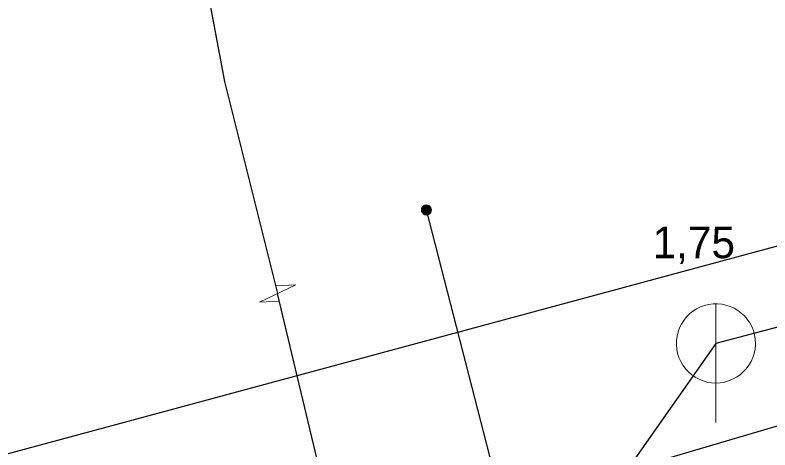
# Model space of a CAD drawing. Extents: x -682839 to -682312, y -994645 to -993949.
# Drawn here: x -682717.39 to -682698.3, y -994076.96 to -994065.98 of the extents above; entities that cross this region are included whole.
import ezdxf

# ---------------------------------------------------------------- set-up
doc = ezdxf.new("R2010")
doc.units = 0
doc.header["$LTSCALE"] = 0.4
doc.layers.add('1', color=7, linetype='Continuous')
for name, color, linetype, lineweight in [('14', 7, 'Continuous', 25), ('17', 7, 'Continuous', 25), ('22', 7, 'Continuous', 13), ('47', 7, 'Continuous', 13), ('9', 7, 'Continuous', 13)]:
    doc.layers.add(name, color=color, linetype=linetype, lineweight=lineweight)

msp = doc.modelspace()

# ---------------------------------------------------------------- linework, layer by layer
at = {"layer": '14'}
msp.add_line((-682699.67, -994074.27), (-682704.43, -994081.039), dxfattribs=at)
msp.add_lwpolyline([(-682670.21, -994066.53), (-682696.629, -994073.469), (-682696.739, -994073.5), (-682699.67, -994074.27)], dxfattribs=at)
at = {"layer": '17'}
for p, q in [((-682705.23, -994077.73), (-682706.989, -994070.899)), ((-682709.273, -994079.188), (-682710.75, -994073.01))]:
    msp.add_line(p, q, dxfattribs=at)
for points in [[(-682704.612, -993949.41), (-682708.09, -993958.105), (-682711.188, -993967.784), (-682713.456, -993979.175), (-682714.892, -993986.737), (-682715.8, -993997.625), (-682717.009, -994008.21), (-682717.083, -994024.577), (-682716.252, -994039.624), (-682714.741, -994053.59), (-682712.096, -994067.653), (-682710.75, -994073.01)], [(-682473.55, -994045.57), (-682522.289, -994043.899), (-682529.616, -994044.905), (-682556.26, -994048.129), (-682661.506, -994061.932), (-682719.074, -994077.464), (-682816.699, -994104.109)], [(-682705.03, -994078.39), (-682696.77, -994075.96), (-682691.829, -994074.544), (-682685.35, -994072.597), (-682672.05, -994068.67), (-682644.92, -994063.19), (-682632.77, -994060.73)]]:
    msp.add_lwpolyline(points, dxfattribs=at)
at = {"layer": '22'}
msp.add_line((-682699.67, -994076.27), (-682699.669, -994073.27), dxfattribs=at)
msp.add_lwpolyline([(-682698.67, -994074.27), (-682698.675, -994074.161), (-682698.693, -994074.053), (-682698.723, -994073.947), (-682698.763, -994073.846), (-682698.815, -994073.749), (-682698.877, -994073.659), (-682698.949, -994073.576), (-682699.029, -994073.502), (-682699.117, -994073.436), (-682699.211, -994073.381), (-682699.311, -994073.336), (-682699.416, -994073.303), (-682699.523, -994073.281), (-682699.632, -994073.271), (-682699.742, -994073.273), (-682699.85, -994073.287), (-682699.957, -994073.312), (-682700.06, -994073.349), (-682700.158, -994073.398), (-682700.25, -994073.456), (-682700.336, -994073.525), (-682700.413, -994073.602), (-682700.482, -994073.688), (-682700.541, -994073.78), (-682700.589, -994073.878), (-682700.626, -994073.981), (-682700.652, -994074.088), (-682700.666, -994074.196), (-682700.669, -994074.306), (-682700.659, -994074.415), (-682700.638, -994074.522), (-682700.604, -994074.626), (-682700.56, -994074.726), (-682700.505, -994074.821), (-682700.439, -994074.909), (-682700.365, -994074.989), (-682700.282, -994075.061), (-682700.192, -994075.123), (-682700.096, -994075.175), (-682699.994, -994075.216), (-682699.889, -994075.246), (-682699.781, -994075.264), (-682699.671, -994075.27), (-682699.562, -994075.264), (-682699.454, -994075.246), (-682699.349, -994075.217), (-682699.247, -994075.176), (-682699.15, -994075.124), (-682699.06, -994075.062), (-682698.977, -994074.991), (-682698.902, -994074.911), (-682698.837, -994074.823), (-682698.781, -994074.729), (-682698.737, -994074.629), (-682698.703, -994074.525), (-682698.681, -994074.417), (-682698.671, -994074.308)], close=True, dxfattribs=at)
at = {"layer": '47'}
msp.add_line((-682710.289, -994072.793), (-682710.799, -994072.815), dxfattribs=at)
msp.add_lwpolyline([(-682710.289, -994072.793), (-682711.21, -994073.226), (-682710.7, -994073.204)], dxfattribs=at)
at = {"layer": '9'}
for points in [[(-682707.115, -994070.899), (-682707.115, -994070.912), (-682707.112, -994070.925), (-682707.11, -994070.938), (-682707.105, -994070.95), (-682707.098, -994070.962), (-682707.092, -994070.973), (-682707.083, -994070.983), (-682707.073, -994070.993), (-682707.063, -994071.001), (-682707.053, -994071.008), (-682707.041, -994071.014), (-682707.029, -994071.019), (-682707.016, -994071.022), (-682707.002, -994071.024), (-682706.99, -994071.026), (-682706.977, -994071.025), (-682706.963, -994071.023), (-682706.951, -994071.02), (-682706.938, -994071.015), (-682706.926, -994071.009), (-682706.916, -994071.002), (-682706.906, -994070.994), (-682706.896, -994070.984), (-682706.887, -994070.974), (-682706.88, -994070.963), (-682706.875, -994070.951), (-682706.87, -994070.939), (-682706.867, -994070.926), (-682706.865, -994070.913), (-682706.862, -994070.9), (-682706.864, -994070.887), (-682706.865, -994070.874), (-682706.869, -994070.861), (-682706.874, -994070.849), (-682706.879, -994070.837), (-682706.887, -994070.826), (-682706.894, -994070.816), (-682706.904, -994070.806), (-682706.914, -994070.798), (-682706.926, -994070.791), (-682706.938, -994070.785), (-682706.95, -994070.78), (-682706.963, -994070.777), (-682706.975, -994070.775), (-682706.989, -994070.774), (-682707.002, -994070.774), (-682707.014, -994070.776), (-682707.027, -994070.779), (-682707.039, -994070.784), (-682707.051, -994070.79), (-682707.063, -994070.797), (-682707.073, -994070.805), (-682707.083, -994070.815), (-682707.09, -994070.825), (-682707.098, -994070.836), (-682707.103, -994070.848), (-682707.108, -994070.86), (-682707.112, -994070.873), (-682707.114, -994070.886)], [(-682707.095, -994070.899), (-682707.095, -994070.91), (-682707.093, -994070.921), (-682707.09, -994070.932), (-682707.087, -994070.942), (-682707.081, -994070.952), (-682707.076, -994070.961), (-682707.068, -994070.97), (-682707.061, -994070.978), (-682707.051, -994070.985), (-682707.043, -994070.991), (-682707.032, -994070.996), (-682707.022, -994071), (-682707.012, -994071.003), (-682707, -994071.006), (-682706.99, -994071.006), (-682706.978, -994071.006), (-682706.968, -994071.004), (-682706.956, -994071.001), (-682706.946, -994070.997), (-682706.936, -994070.992), (-682706.928, -994070.986), (-682706.919, -994070.979), (-682706.911, -994070.971), (-682706.904, -994070.962), (-682706.897, -994070.953), (-682706.892, -994070.943), (-682706.889, -994070.933), (-682706.886, -994070.922), (-682706.884, -994070.911), (-682706.882, -994070.9), (-682706.882, -994070.889), (-682706.884, -994070.878), (-682706.887, -994070.867), (-682706.892, -994070.857), (-682706.897, -994070.847), (-682706.902, -994070.838), (-682706.909, -994070.829), (-682706.918, -994070.821), (-682706.926, -994070.814), (-682706.936, -994070.808), (-682706.946, -994070.803), (-682706.955, -994070.799), (-682706.967, -994070.796), (-682706.977, -994070.794), (-682706.989, -994070.794), (-682707, -994070.793), (-682707.011, -994070.795), (-682707.022, -994070.798), (-682707.031, -994070.802), (-682707.041, -994070.807), (-682707.051, -994070.813), (-682707.059, -994070.82), (-682707.068, -994070.828), (-682707.075, -994070.837), (-682707.08, -994070.846), (-682707.085, -994070.856), (-682707.09, -994070.866), (-682707.093, -994070.877), (-682707.095, -994070.888)], [(-682707.076, -994070.899), (-682707.076, -994070.908), (-682707.075, -994070.917), (-682707.071, -994070.926), (-682707.068, -994070.934), (-682707.065, -994070.942), (-682707.059, -994070.95), (-682707.053, -994070.957), (-682707.048, -994070.963), (-682707.041, -994070.969), (-682707.032, -994070.974), (-682707.024, -994070.978), (-682707.017, -994070.981), (-682707.007, -994070.984), (-682706.999, -994070.985), (-682706.99, -994070.987), (-682706.98, -994070.986), (-682706.972, -994070.985), (-682706.963, -994070.982), (-682706.955, -994070.979), (-682706.946, -994070.975), (-682706.938, -994070.97), (-682706.931, -994070.964), (-682706.926, -994070.958), (-682706.919, -994070.951), (-682706.914, -994070.943), (-682706.911, -994070.935), (-682706.907, -994070.927), (-682706.904, -994070.918), (-682706.904, -994070.909), (-682706.901, -994070.9), (-682706.902, -994070.891), (-682706.904, -994070.882), (-682706.906, -994070.873), (-682706.909, -994070.865), (-682706.914, -994070.857), (-682706.919, -994070.849), (-682706.924, -994070.842), (-682706.931, -994070.836), (-682706.938, -994070.83), (-682706.946, -994070.825), (-682706.953, -994070.821), (-682706.962, -994070.818), (-682706.97, -994070.815), (-682706.98, -994070.814), (-682706.989, -994070.813), (-682706.997, -994070.813), (-682707.007, -994070.814), (-682707.016, -994070.817), (-682707.024, -994070.82), (-682707.031, -994070.824), (-682707.039, -994070.829), (-682707.046, -994070.835), (-682707.053, -994070.841), (-682707.058, -994070.848), (-682707.063, -994070.856), (-682707.068, -994070.864), (-682707.071, -994070.872), (-682707.073, -994070.881), (-682707.075, -994070.89)], [(-682707.056, -994070.899), (-682707.056, -994070.906), (-682707.054, -994070.913), (-682707.053, -994070.92), (-682707.051, -994070.926), (-682707.048, -994070.932), (-682707.044, -994070.938), (-682707.039, -994070.944), (-682707.034, -994070.949), (-682707.029, -994070.953), (-682707.022, -994070.957), (-682707.017, -994070.96), (-682707.011, -994070.963), (-682707.004, -994070.964), (-682706.997, -994070.967), (-682706.99, -994070.967), (-682706.982, -994070.967), (-682706.975, -994070.965), (-682706.968, -994070.964), (-682706.963, -994070.961), (-682706.955, -994070.958), (-682706.951, -994070.954), (-682706.945, -994070.95), (-682706.94, -994070.945), (-682706.936, -994070.939), (-682706.931, -994070.933), (-682706.928, -994070.927), (-682706.926, -994070.921), (-682706.924, -994070.914), (-682706.923, -994070.907), (-682706.921, -994070.9), (-682706.921, -994070.893), (-682706.923, -994070.886), (-682706.924, -994070.879), (-682706.928, -994070.873), (-682706.931, -994070.866), (-682706.934, -994070.861), (-682706.938, -994070.855), (-682706.943, -994070.85), (-682706.95, -994070.846), (-682706.955, -994070.842), (-682706.962, -994070.839), (-682706.968, -994070.836), (-682706.975, -994070.834), (-682706.982, -994070.833), (-682706.989, -994070.833), (-682706.995, -994070.833), (-682707.002, -994070.833), (-682707.009, -994070.835), (-682707.016, -994070.838), (-682707.022, -994070.841), (-682707.027, -994070.845), (-682707.034, -994070.849), (-682707.039, -994070.854), (-682707.043, -994070.86), (-682707.046, -994070.865), (-682707.049, -994070.872), (-682707.053, -994070.878), (-682707.053, -994070.885), (-682707.056, -994070.892)], [(-682707.036, -994070.899), (-682707.036, -994070.904), (-682707.036, -994070.909), (-682707.034, -994070.914), (-682707.032, -994070.918), (-682707.031, -994070.923), (-682707.027, -994070.927), (-682707.024, -994070.93), (-682707.021, -994070.934), (-682707.017, -994070.937), (-682707.014, -994070.94), (-682707.009, -994070.942), (-682707.004, -994070.944), (-682707, -994070.945), (-682706.995, -994070.947), (-682706.99, -994070.947), (-682706.985, -994070.947), (-682706.98, -994070.946), (-682706.975, -994070.945), (-682706.97, -994070.943), (-682706.965, -994070.941), (-682706.962, -994070.938), (-682706.958, -994070.935), (-682706.955, -994070.931), (-682706.951, -994070.928), (-682706.948, -994070.924), (-682706.946, -994070.919), (-682706.945, -994070.915), (-682706.943, -994070.91), (-682706.943, -994070.905), (-682706.941, -994070.9), (-682706.941, -994070.895), (-682706.943, -994070.89), (-682706.943, -994070.885), (-682706.946, -994070.881), (-682706.948, -994070.876), (-682706.951, -994070.872), (-682706.953, -994070.868), (-682706.956, -994070.865), (-682706.96, -994070.862), (-682706.965, -994070.859), (-682706.97, -994070.857), (-682706.973, -994070.855), (-682706.978, -994070.854), (-682706.983, -994070.853), (-682706.989, -994070.853), (-682706.994, -994070.853), (-682706.999, -994070.854), (-682707.004, -994070.854), (-682707.007, -994070.856), (-682707.012, -994070.858), (-682707.017, -994070.861), (-682707.019, -994070.864), (-682707.024, -994070.867), (-682707.026, -994070.871), (-682707.029, -994070.875), (-682707.031, -994070.88), (-682707.034, -994070.884), (-682707.034, -994070.889), (-682707.036, -994070.894)], [(-682707.016, -994070.899), (-682707.016, -994070.902), (-682707.017, -994070.905), (-682707.016, -994070.907), (-682707.014, -994070.91), (-682707.014, -994070.913), (-682707.012, -994070.915), (-682707.009, -994070.917), (-682707.007, -994070.919), (-682707.005, -994070.921), (-682707.004, -994070.923), (-682707, -994070.925), (-682706.997, -994070.926), (-682706.995, -994070.926), (-682706.992, -994070.927), (-682706.99, -994070.927), (-682706.987, -994070.927), (-682706.983, -994070.927), (-682706.98, -994070.926), (-682706.978, -994070.925), (-682706.975, -994070.924), (-682706.973, -994070.922), (-682706.97, -994070.92), (-682706.968, -994070.918), (-682706.968, -994070.916), (-682706.965, -994070.914), (-682706.965, -994070.911), (-682706.963, -994070.908), (-682706.963, -994070.906), (-682706.962, -994070.903), (-682706.96, -994070.9), (-682706.962, -994070.897), (-682706.962, -994070.894), (-682706.963, -994070.891), (-682706.963, -994070.889), (-682706.965, -994070.886), (-682706.967, -994070.884), (-682706.968, -994070.881), (-682706.97, -994070.879), (-682706.973, -994070.878), (-682706.975, -994070.876), (-682706.977, -994070.875), (-682706.98, -994070.874), (-682706.982, -994070.873), (-682706.985, -994070.873), (-682706.989, -994070.872), (-682706.992, -994070.873), (-682706.995, -994070.872), (-682706.997, -994070.874), (-682707, -994070.874), (-682707.002, -994070.875), (-682707.004, -994070.877), (-682707.007, -994070.878), (-682707.009, -994070.88), (-682707.011, -994070.883), (-682707.012, -994070.885), (-682707.014, -994070.888), (-682707.014, -994070.89), (-682707.016, -994070.893), (-682707.016, -994070.896)], [(-682706.997, -994070.899), (-682706.997, -994070.901), (-682706.997, -994070.901), (-682706.995, -994070.901), (-682706.995, -994070.903), (-682706.997, -994070.904), (-682706.995, -994070.904), (-682706.995, -994070.904), (-682706.995, -994070.906), (-682706.995, -994070.906), (-682706.994, -994070.907), (-682706.992, -994070.907), (-682706.992, -994070.907), (-682706.992, -994070.908), (-682706.99, -994070.908), (-682706.99, -994070.908), (-682706.989, -994070.908), (-682706.987, -994070.908), (-682706.987, -994070.907), (-682706.987, -994070.907), (-682706.985, -994070.907), (-682706.985, -994070.906), (-682706.985, -994070.906), (-682706.983, -994070.905), (-682706.983, -994070.905), (-682706.982, -994070.904), (-682706.982, -994070.903), (-682706.98, -994070.902), (-682706.98, -994070.902), (-682706.98, -994070.901), (-682706.98, -994070.9), (-682706.98, -994070.899), (-682706.98, -994070.898), (-682706.98, -994070.898), (-682706.982, -994070.897), (-682706.982, -994070.896), (-682706.982, -994070.895), (-682706.982, -994070.895), (-682706.983, -994070.894), (-682706.983, -994070.894), (-682706.985, -994070.893), (-682706.985, -994070.893), (-682706.987, -994070.892), (-682706.987, -994070.892), (-682706.987, -994070.892), (-682706.989, -994070.892), (-682706.99, -994070.892), (-682706.99, -994070.892), (-682706.99, -994070.892), (-682706.992, -994070.893), (-682706.992, -994070.892), (-682706.994, -994070.894), (-682706.994, -994070.894), (-682706.995, -994070.894), (-682706.995, -994070.894), (-682706.995, -994070.896), (-682706.995, -994070.897), (-682706.995, -994070.898), (-682706.997, -994070.898), (-682706.997, -994070.899)]]:
    msp.add_lwpolyline(points, close=True, dxfattribs=at)

# ---------------------------------------------------------------- texts
at = {"layer": '1'}
msp.add_text('1,75', height=0.8, dxfattribs=at).set_placement((-682701.269, -994072.117))

doc.saveas('drawing.dxf')
